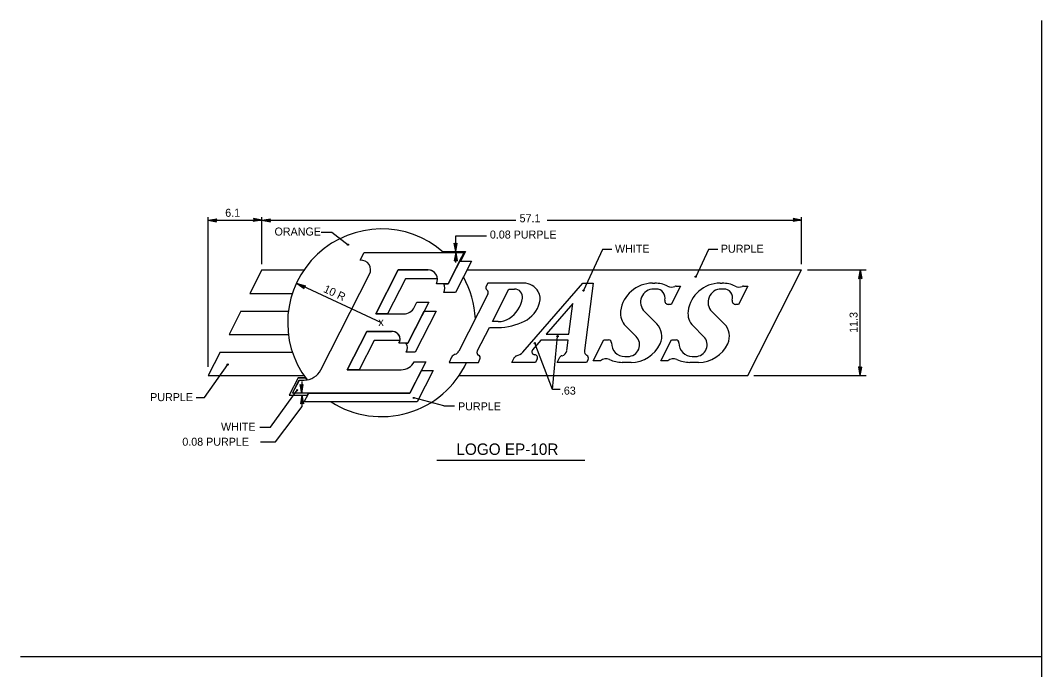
# Model space of a CAD drawing. Extents: x 10268197 to 10269179, y 2141503 to 2142677.
# Drawn here: x 10268584.7 to 10268661.7, y 2142006.1 to 2142055.1 of the extents above; entities that cross this region are included whole.
import ezdxf

# ---------------------------------------------------------------- set-up
doc = ezdxf.new("R2010")
doc.units = 0
for name, color, linetype in [('1', 7, 'Continuous'), ('Default', 7, 'Continuous'), ('GSBWFill', 7, 'Continuous'), ('NonPlottingEle_dp', 7, 'Continuous'), ('TextDetails', 7, 'Continuous')]:
    doc.layers.add(name, color=color, linetype=linetype)

msp = doc.modelspace()

# ---------------------------------------------------------------- linework, layer by layer
at = {"layer": '1'}
for p, q in [((10268598.891, 2142028.973), (10268598.891, 2142040.27)), ((10268598.891, 2142040.049), (10268622.093, 2142040.049)), ((10268602.945, 2142036.73), (10268602.945, 2142040.27)), ((10268624.448, 2142040.049), (10268643.648, 2142040.049)), ((10268643.648, 2142036.73), (10268643.648, 2142040.27)), ((10268607.422, 2142039.137), (10268608.223, 2142039.137)), ((10268608.223, 2142039.137), (10268609.444, 2142038.195)), ((10268617.571, 2142038.871), (10268619.879, 2142038.871)), ((10268617.571, 2142037.7), (10268617.571, 2142038.871)), ((10268617.571, 2142036.858), (10268617.571, 2142037.621)), ((10268628.633, 2142037.839), (10268627.193, 2142034.732)), ((10268629.335, 2142037.839), (10268628.633, 2142037.839)), ((10268636.613, 2142037.839), (10268635.659, 2142035.781)), ((10268637.316, 2142037.839), (10268636.613, 2142037.839)), ((10268644.09, 2142036.288), (10268648.515, 2142036.288)), ((10268648.072, 2142028.324), (10268648.072, 2142036.288)), ((10268611.97, 2142032.306), (10268605.617, 2142035.268)), ((10268624.856, 2142027.267), (10268625.243, 2142031.286)), ((10268624.856, 2142027.267), (10268623.528, 2142030.757)), ((10268598.613, 2142026.677), (10268600.371, 2142029.156)), ((10268640.032, 2142028.324), (10268648.515, 2142028.324)), ((10268605.969, 2142027.883), (10268605.969, 2142027.004)), ((10268625.429, 2142027.267), (10268624.856, 2142027.267)), ((10268597.999, 2142026.677), (10268598.613, 2142026.677)), ((10268603.595, 2142024.433), (10268605.602, 2142027.222)), ((10268605.969, 2142026.847), (10268605.969, 2142025.974)), ((10268616.672, 2142026.042), (10268614.4, 2142026.636)), ((10268605.369, 2142025.182), (10268605.969, 2142025.974)), ((10268616.672, 2142026.042), (10268617.473, 2142026.042)), ((10268603.965, 2142023.328), (10268605.369, 2142025.182)), ((10268602.794, 2142024.433), (10268603.595, 2142024.433)), ((10268602.841, 2142023.328), (10268603.965, 2142023.328))]:
    msp.add_line(p, q, dxfattribs=at)
for centre, radius in [((10268609.443, 2142038.194), 0.0442), ((10268635.659, 2142035.78), 0.0442), ((10268627.193, 2142034.731), 0.0442), ((10268625.243, 2142031.286), 0.0518), ((10268623.528, 2142030.757), 0.0518), ((10268600.371, 2142029.155), 0.0442), ((10268605.602, 2142027.221), 0.0442), ((10268614.4, 2142026.635), 0.0442)]:
    msp.add_circle(centre, radius, dxfattribs=at)
at = {"layer": 'Default'}
for p, q in [((10268598.891, 2142040.049), (10268599.538, 2142040.151)), ((10268598.891, 2142040.049), (10268599.51, 2142040.092)), ((10268598.891, 2142040.049), (10268599.534, 2142039.923)), ((10268598.891, 2142040.049), (10268599.509, 2142039.983)), ((10268599.486, 2142040.038), (10268599.538, 2142040.151)), ((10268599.534, 2142039.923), (10268599.486, 2142040.038)), ((10268602.349, 2142040.058), (10268602.298, 2142039.946)), ((10268602.945, 2142040.049), (10268602.298, 2142039.946)), ((10268602.945, 2142040.049), (10268602.302, 2142040.173)), ((10268602.302, 2142040.173), (10268602.349, 2142040.058)), ((10268602.945, 2142040.049), (10268602.325, 2142040.005)), ((10268602.945, 2142040.049), (10268602.326, 2142040.113)), ((10268602.945, 2142040.049), (10268603.592, 2142040.151)), ((10268602.945, 2142040.049), (10268603.564, 2142040.092)), ((10268602.945, 2142040.049), (10268603.587, 2142039.923)), ((10268602.945, 2142040.049), (10268603.563, 2142039.983)), ((10268603.54, 2142040.038), (10268603.592, 2142040.151)), ((10268603.587, 2142039.923), (10268603.54, 2142040.038)), ((10268643.052, 2142040.058), (10268643.001, 2142039.946)), ((10268643.648, 2142040.049), (10268643.001, 2142039.946)), ((10268643.648, 2142040.049), (10268643.005, 2142040.173)), ((10268643.005, 2142040.173), (10268643.052, 2142040.058)), ((10268643.648, 2142040.049), (10268643.029, 2142040.005)), ((10268643.648, 2142040.049), (10268643.03, 2142040.113)), ((10268617.572, 2142037.669), (10268617.448, 2142038.312)), ((10268617.448, 2142038.312), (10268617.562, 2142038.265)), ((10268617.572, 2142037.669), (10268617.508, 2142038.288)), ((10268617.562, 2142038.265), (10268617.675, 2142038.316)), ((10268617.572, 2142037.669), (10268617.675, 2142038.316)), ((10268617.572, 2142037.669), (10268617.616, 2142038.289)), ((10268610.369, 2142037.022), (10268610.671, 2142037.615)), ((10268610.671, 2142037.615), (10268618.192, 2142037.615)), ((10268616.576, 2142037.681), (10268618.3, 2142037.681)), ((10268618.192, 2142037.615), (10268616.988, 2142035.25)), ((10268617.572, 2142037.617), (10268617.448, 2142036.973)), ((10268617.572, 2142037.617), (10268617.508, 2142036.998)), ((10268617.572, 2142037.617), (10268617.675, 2142036.97)), ((10268617.572, 2142037.617), (10268617.616, 2142036.997)), ((10268618.3, 2142037.681), (10268617.928, 2142036.952)), ((10268616.986, 2142035.247), (10268617.855, 2142036.952)), ((10268616.986, 2142035.247), (10268617.855, 2142036.952)), ((10268617.448, 2142036.973), (10268617.562, 2142037.021)), ((10268618.748, 2142036.952), (10268617.543, 2142034.586)), ((10268618.748, 2142036.952), (10268617.543, 2142034.586)), ((10268617.562, 2142037.021), (10268617.675, 2142036.97)), ((10268617.855, 2142036.952), (10268618.748, 2142036.952)), ((10268617.855, 2142036.952), (10268618.748, 2142036.952)), ((10268602.945, 2142036.288), (10268602.044, 2142034.518)), ((10268602.945, 2142036.288), (10268606.117, 2142036.288)), ((10268607.396, 2142028.755), (10268611.068, 2142035.962)), ((10268613.22, 2142036.288), (10268611.529, 2142032.97)), ((10268611.529, 2142032.97), (10268613.22, 2142036.288)), ((10268611.529, 2142032.97), (10268613.22, 2142036.288)), ((10268615.475, 2142036.288), (10268613.22, 2142036.288)), ((10268613.22, 2142036.288), (10268615.475, 2142036.288)), ((10268613.22, 2142036.288), (10268615.475, 2142036.288)), ((10268618.409, 2142036.288), (10268643.648, 2142036.288)), ((10268639.59, 2142028.324), (10268643.648, 2142036.288)), ((10268648.072, 2142036.288), (10268647.947, 2142035.645)), ((10268648.072, 2142036.288), (10268648.008, 2142035.67)), ((10268648.072, 2142036.288), (10268648.175, 2142035.641)), ((10268648.072, 2142036.288), (10268648.116, 2142035.668)), ((10268605.617, 2142035.268), (10268606.247, 2142035.088)), ((10268605.617, 2142035.268), (10268606.147, 2142034.884)), ((10268605.617, 2142035.268), (10268606.15, 2142034.949)), ((10268605.617, 2142035.268), (10268606.197, 2142035.046)), ((10268606.147, 2142034.884), (10268606.152, 2142035.008)), ((10268606.152, 2142035.008), (10268606.247, 2142035.088)), ((10268613.776, 2142035.624), (10268612.423, 2142032.97)), ((10268613.776, 2142035.624), (10268612.423, 2142032.97)), ((10268616.182, 2142035.624), (10268613.776, 2142035.624)), ((10268616.182, 2142035.624), (10268613.776, 2142035.624)), ((10268616.988, 2142035.25), (10268616.102, 2142035.25)), ((10268616.657, 2142035.247), (10268616.986, 2142035.247)), ((10268616.657, 2142035.247), (10268616.986, 2142035.247)), ((10268619.978, 2142035.292), (10268619.857, 2142035.056)), ((10268622.687, 2142035.292), (10268619.978, 2142035.292)), ((10268622.62, 2142030.096), (10268627.137, 2142035.292)), ((10268627.137, 2142035.292), (10268627.934, 2142035.292)), ((10268627.934, 2142035.292), (10268627.271, 2142030.201)), ((10268632.409, 2142035.292), (10268632.576, 2142035.292)), ((10268634.513, 2142035.071), (10268633.81, 2142033.691)), ((10268634.182, 2142035.071), (10268634.513, 2142035.071)), ((10268637.497, 2142035.292), (10268637.665, 2142035.292)), ((10268639.601, 2142035.071), (10268638.898, 2142033.691)), ((10268639.269, 2142035.071), (10268639.601, 2142035.071)), ((10268647.947, 2142035.645), (10268648.062, 2142035.692)), ((10268648.062, 2142035.692), (10268648.175, 2142035.641)), ((10268602.044, 2142034.518), (10268605.246, 2142034.518)), ((10268617.543, 2142034.586), (10268616.658, 2142034.586)), ((10268617.543, 2142034.586), (10268616.658, 2142034.586)), ((10268619.986, 2142034.456), (10268617.795, 2142030.157)), ((10268620.325, 2142032.394), (10268621.577, 2142034.85)), ((10268621.577, 2142034.85), (10268622.003, 2142034.85)), ((10268632.689, 2142034.85), (10268632.499, 2142034.85)), ((10268637.777, 2142034.85), (10268637.587, 2142034.85)), ((10268615.524, 2142033.855), (10268613.946, 2142030.758)), ((10268614.434, 2142033.453), (10268614.639, 2142033.855)), ((10268614.639, 2142033.855), (10268615.524, 2142033.855)), ((10268626.396, 2142033.766), (10268624.377, 2142031.443)), ((10268626.094, 2142031.443), (10268626.396, 2142033.766)), ((10268633.81, 2142033.691), (10268633.589, 2142033.691)), ((10268638.898, 2142033.691), (10268638.677, 2142033.691)), ((10268601.369, 2142033.191), (10268600.468, 2142031.421)), ((10268601.369, 2142033.191), (10268604.946, 2142033.191)), ((10268611.529, 2142032.97), (10268613.646, 2142032.97)), ((10268612.423, 2142032.97), (10268611.529, 2142032.97)), ((10268612.423, 2142032.97), (10268611.529, 2142032.97)), ((10268613.946, 2142030.758), (10268615.186, 2142033.191)), ((10268613.946, 2142030.758), (10268615.186, 2142033.191)), ((10268616.08, 2142033.191), (10268614.502, 2142030.094)), ((10268616.08, 2142033.191), (10268614.502, 2142030.094)), ((10268615.186, 2142033.191), (10268616.08, 2142033.191)), ((10268615.186, 2142033.191), (10268616.08, 2142033.191)), ((10268631.795, 2142033.15), (10268632.722, 2142032.223)), ((10268636.883, 2142033.15), (10268637.811, 2142032.223)), ((10268619.185, 2142030.157), (10268620.1, 2142031.952)), ((10268620.1, 2142031.952), (10268620.763, 2142031.952)), ((10268620.763, 2142032.394), (10268620.325, 2142032.394)), ((10268631.17, 2142031.273), (10268630.374, 2142032.068)), ((10268636.258, 2142031.273), (10268635.462, 2142032.068)), ((10268600.468, 2142031.421), (10268604.946, 2142031.421)), ((10268610.854, 2142031.643), (10268609.388, 2142028.767)), ((10268609.388, 2142028.767), (10268610.854, 2142031.643)), ((10268609.388, 2142028.767), (10268610.854, 2142031.643)), ((10268612.795, 2142031.643), (10268610.854, 2142031.643)), ((10268610.854, 2142031.643), (10268612.712, 2142031.636)), ((10268610.854, 2142031.643), (10268612.712, 2142031.636)), ((10268624.377, 2142031.443), (10268626.094, 2142031.443)), ((10268611.408, 2142030.977), (10268610.282, 2142028.767)), ((10268611.408, 2142030.977), (10268610.282, 2142028.767)), ((10268613.362, 2142030.971), (10268611.408, 2142030.977)), ((10268613.362, 2142030.971), (10268611.408, 2142030.977)), ((10268613.946, 2142030.758), (10268613.28, 2142030.758)), ((10268613.807, 2142030.758), (10268613.946, 2142030.758)), ((10268613.807, 2142030.758), (10268613.946, 2142030.758)), ((10268623.993, 2142031), (10268623.352, 2142030.264)), ((10268626.049, 2142031), (10268623.993, 2142031)), ((10268625.944, 2142030.201), (10268626.049, 2142031)), ((10268627.931, 2142029.43), (10268628.734, 2142031.007)), ((10268628.734, 2142031.007), (10268629.089, 2142031.007)), ((10268633.018, 2142029.43), (10268633.822, 2142031.007)), ((10268633.822, 2142031.007), (10268634.177, 2142031.007)), ((10268599.792, 2142030.094), (10268598.891, 2142028.324)), ((10268599.792, 2142030.094), (10268605.246, 2142030.094)), ((10268614.502, 2142030.094), (10268613.838, 2142030.094)), ((10268614.502, 2142030.094), (10268613.838, 2142030.094)), ((10268617.257, 2142029.71), (10268617.058, 2142029.319)), ((10268619.271, 2142029.319), (10268619.391, 2142029.556)), ((10268621.806, 2142029.319), (10268621.998, 2142029.698)), ((10268623.706, 2142029.575), (10268623.575, 2142029.319)), ((10268625.22, 2142029.319), (10268625.415, 2142029.704)), ((10268627.548, 2142029.547), (10268627.432, 2142029.319)), ((10268630.305, 2142029.762), (10268630.544, 2142029.762)), ((10268635.393, 2142029.762), (10268635.632, 2142029.762)), ((10268615.315, 2142029.362), (10268614.11, 2142026.997)), ((10268614.43, 2142029.362), (10268615.315, 2142029.362)), ((10268617.058, 2142029.319), (10268619.271, 2142029.319)), ((10268623.575, 2142029.319), (10268621.806, 2142029.319)), ((10268627.432, 2142029.319), (10268625.22, 2142029.319)), ((10268628.468, 2142029.43), (10268627.931, 2142029.43)), ((10268630.782, 2142029.319), (10268630.117, 2142029.319)), ((10268633.556, 2142029.43), (10268633.018, 2142029.43)), ((10268635.87, 2142029.319), (10268635.205, 2142029.319)), ((10268648.072, 2142028.324), (10268647.969, 2142028.971)), ((10268648.082, 2142028.92), (10268647.969, 2142028.971)), ((10268648.072, 2142028.324), (10268648.029, 2142028.943)), ((10268648.072, 2142028.324), (10268648.197, 2142028.967)), ((10268648.072, 2142028.324), (10268648.136, 2142028.942)), ((10268648.197, 2142028.967), (10268648.082, 2142028.92)), ((10268598.891, 2142028.324), (10268606.117, 2142028.324)), ((10268605.671, 2142028.155), (10268605.005, 2142026.847)), ((10268605.671, 2142028.155), (10268606.235, 2142028.155)), ((10268609.388, 2142028.767), (10268613.449, 2142028.767)), ((10268610.282, 2142028.767), (10268609.388, 2142028.767)), ((10268610.282, 2142028.767), (10268609.388, 2142028.767)), ((10268614.11, 2142026.997), (10268614.977, 2142028.699)), ((10268614.11, 2142026.997), (10268614.977, 2142028.699)), ((10268615.871, 2142028.699), (10268614.665, 2142026.333)), ((10268615.871, 2142028.699), (10268614.665, 2142026.333)), ((10268614.977, 2142028.699), (10268615.871, 2142028.699)), ((10268614.977, 2142028.699), (10268615.871, 2142028.699)), ((10268617.823, 2142028.324), (10268639.59, 2142028.324)), ((10268605.261, 2142026.997), (10268605.763, 2142027.982)), ((10268605.763, 2142027.982), (10268606.135, 2142027.982)), ((10268605.969, 2142027.004), (10268605.844, 2142027.646)), ((10268605.844, 2142027.646), (10268605.959, 2142027.599)), ((10268605.969, 2142027.004), (10268605.905, 2142027.621)), ((10268605.959, 2142027.599), (10268606.072, 2142027.65)), ((10268605.969, 2142027.004), (10268606.072, 2142027.65)), ((10268605.969, 2142027.004), (10268606.012, 2142027.623)), ((10268605.005, 2142026.847), (10268606.393, 2142026.847)), ((10268614.11, 2142026.997), (10268605.261, 2142026.997)), ((10268605.969, 2142026.847), (10268605.866, 2142026.2)), ((10268605.969, 2142026.847), (10268605.926, 2142026.227)), ((10268605.969, 2142026.847), (10268606.094, 2142026.203)), ((10268605.969, 2142026.847), (10268606.034, 2142026.228)), ((10268606.146, 2142026.333), (10268606.484, 2142026.997)), ((10268606.146, 2142026.333), (10268606.484, 2142026.997)), ((10268606.484, 2142026.997), (10268614.11, 2142026.997)), ((10268606.484, 2142026.997), (10268614.11, 2142026.997)), ((10268605.979, 2142026.251), (10268605.866, 2142026.2)), ((10268606.094, 2142026.203), (10268605.979, 2142026.251)), ((10268614.665, 2142026.333), (10268606.146, 2142026.333)), ((10268614.665, 2142026.333), (10268606.146, 2142026.333)), ((10268616.143, 2142021.947), (10268627.292, 2142021.947))]:
    msp.add_line(p, q, dxfattribs=at)
for points in [[(10268616.576, 2142037.681), (10268618.3, 2142037.681), (10268617.928, 2142036.952), (10268617.855, 2142036.952), (10268618.192, 2142037.615), (10268616.652, 2142037.614)], [(10268606.235, 2142028.155), (10268605.671, 2142028.155), (10268605.005, 2142026.847), (10268606.393, 2142026.847), (10268606.484, 2142026.997), (10268605.261, 2142026.997), (10268605.777, 2142027.982), (10268606.14, 2142027.982), (10268606.352, 2142027.999)]]:
    msp.add_lwpolyline(points, close=True, dxfattribs=at)
for centre, radius, start, end in [((10268611.97, 2142032.305), 7.079, 48.59038, 217.4727), ((10268610.417, 2142036.293), 0.73, 332.99985, 93.80449), ((10268615.475, 2142035.579), 0.708, 332.20885, 90), ((10268615.475, 2142035.579), 0.708, 3.58332, 90), ((10268615.475, 2142035.579), 0.708, 3.58332, 90), ((10268611.97, 2142032.305), 7.079, 2.42356, 29.27706), ((10268616.031, 2142034.916), 0.708, 332.20885, 27.91266), ((10268616.031, 2142034.916), 0.708, 332.20885, 27.91266), ((10268620.054, 2142034.955), 0.221, 152.97842, 231.16017), ((10268622.687, 2142034.031), 1.261, 29.43149, 90), ((10268632.409, 2142032.858), 2.433, 90, 172.30892), ((10268632.576, 2142033.08), 2.212, 64.08957, 90), ((10268633.833, 2142035.666), 0.664, 244.08957, 292.03474), ((10268634.182, 2142034.805), 0.265, 90, 112.03474), ((10268637.496, 2142032.858), 2.433, 90, 172.30892), ((10268637.664, 2142033.08), 2.212, 64.08957, 90), ((10268638.921, 2142035.666), 0.664, 244.08957, 292.03474), ((10268639.269, 2142034.805), 0.265, 90, 112.03474), ((10268619.749, 2142034.576), 0.265, 333.00266, 51.16017), ((10268620.407, 2142034.502), 2.212, 302.42062, 351.07601), ((10268622.003, 2142034.252), 0.597, 351.07601, 90), ((10268622.822, 2142034.107), 1.106, 344.70738, 29.43149), ((10268632.499, 2142033.854), 0.995, 90, 225), ((10268632.689, 2142034.186), 0.664, 345.69149, 90), ((10268637.587, 2142033.854), 0.995, 90, 225), ((10268637.777, 2142034.186), 0.664, 345.69149, 90), ((10268613.646, 2142033.854), 0.885, 270, 332.98829), ((10268621.755, 2142034.398), 2.212, 296.64315, 344.70738), ((10268633.589, 2142033.956), 0.265, 165.69149, 270), ((10268638.677, 2142033.956), 0.265, 165.69149, 270), ((10268620.763, 2142033.942), 1.548, 270, 302.42062), ((10268631.312, 2142033.006), 1.327, 172.30892, 225), ((10268636.4, 2142033.006), 1.327, 172.30892, 225), ((10268620.763, 2142036.376), 4.424, 270, 296.64315), ((10268631.784, 2142031.284), 1.327, 334.94996, 45), ((10268636.872, 2142031.284), 1.327, 334.94996, 45), ((10268612.795, 2142031.066), 0.575, 350.35016, 98.33436), ((10268612.795, 2142031.066), 0.575, 350.35016, 98.33436), ((10268612.795, 2142031.066), 0.575, 327.42103, 90), ((10268630.544, 2142030.646), 0.885, 270, 45), ((10268635.632, 2142030.646), 0.885, 270, 45), ((10268613.354, 2142030.403), 0.575, 327.42103, 37.97987), ((10268613.354, 2142030.403), 0.575, 327.42103, 37.97987), ((10268629.089, 2142030.785), 0.221, 358.66645, 90), ((10268630.306, 2142030.757), 0.995, 178.66645, 270), ((10268630.782, 2142031.752), 2.433, 270, 334.94996), ((10268634.177, 2142030.785), 0.221, 358.66645, 90), ((10268635.394, 2142030.757), 0.995, 178.66645, 270), ((10268635.87, 2142031.752), 2.433, 270, 334.94996), ((10268617.651, 2142029.508), 0.442, 106.43168, 152.97425), ((10268617.401, 2142030.357), 0.442, 286.43167, 332.99588), ((10268619.382, 2142030.056), 0.221, 152.98839, 244.78323), ((10268619.193, 2142029.656), 0.221, 333.02391, 64.78322), ((10268622.195, 2142029.597), 0.221, 102.71621, 153.02391), ((10268621.952, 2142030.676), 0.885, 282.71621, 318.99659), ((10268623.519, 2142030.117), 0.221, 138.98241, 268.68694), ((10268623.509, 2142029.675), 0.221, 332.97842, 88.68694), ((10268625.612, 2142029.602), 0.221, 99.2397, 153.02391), ((10268625.506, 2142030.257), 0.442, 279.2397, 352.56317), ((10268627.622, 2142030.155), 0.354, 172.58839, 241.86732), ((10268627.351, 2142029.647), 0.221, 332.97842, 61.86732), ((10268628.892, 2142028.978), 0.619, 64.37946, 133.18921), ((10268633.98, 2142028.978), 0.619, 64.37946, 133.18921), ((10268611.97, 2142032.305), 7.079, 237.53826, 335.04698), ((10268613.448, 2142029.872), 1.106, 270, 332.5096), ((10268630.116, 2142031.531), 2.212, 244.37946, 270), ((10268635.204, 2142031.531), 2.212, 244.37946, 270), ((10268606.135, 2142029.398), 1.416, 270, 332.99913)]:
    msp.add_arc(centre, radius, start, end, dxfattribs=at)
at = {"layer": 'NonPlottingEle_dp'}
for p, q in [((10268661.739, 2142055.108), (10268661.739, 2141959.108)), ((10268661.739, 2142007.108), (10268584.739, 2142007.108))]:
    msp.add_line(p, q, dxfattribs=at)

# ---------------------------------------------------------------- texts
at = {"layer": '1'}
for s, height, p in [('6.1', 0.6037, (10268600.182, 2142040.3)), ('57.1', 0.6037, (10268622.38, 2142039.887)), ('ORANGE', 0.6037, (10268603.901, 2142038.883)), ('0.08 PURPLE', 0.60368, (10268620.139, 2142038.657)), ('WHITE', 0.6037, (10268629.574, 2142037.588)), ('PURPLE', 0.6037, (10268637.555, 2142037.588)), ('x', 0.604, (10268611.73, 2142032.07)), ('.63', 0.6037, (10268625.493, 2142026.886)), ('PURPLE', 0.6037, (10268594.521, 2142026.395)), ('PURPLE', 0.6037, (10268617.74, 2142025.7)), ('WHITE', 0.6037, (10268599.865, 2142024.162)), ('0.08 PURPLE', 0.60368, (10268596.948, 2142023.031))]:
    msp.add_text(s, height=height, dxfattribs=at).set_placement(p)
for s, rotation, p in [('10 R', 334.99906, (10268607.538, 2142034.646)), ('11.3', 90, (10268647.865, 2142031.546))]:
    msp.add_text(s, height=0.6037, rotation=rotation, dxfattribs=at).set_placement(p)
at = {"layer": 'GSBWFill'}
for s, p in [('reportName:OOCEA10', (10268635.81, 2142036.076)), ('tableTextHeight:0.0500', (10268635.81, 2142036.076)), ('plotScale:50', (10268635.811, 2142036.076)), ('letterPositions:2', (10268635.81, 2142036.076)), ('inchesDisplay:0', (10268635.811, 2142036.076))]:
    msp.add_text(s, height=0.000333, dxfattribs=at).set_placement(p)
at = {"layer": 'TextDetails'}
msp.add_text('LOGO EP-10R', height=0.8624, dxfattribs=at).set_placement((10268617.616, 2142022.339))

doc.saveas('drawing.dxf')
